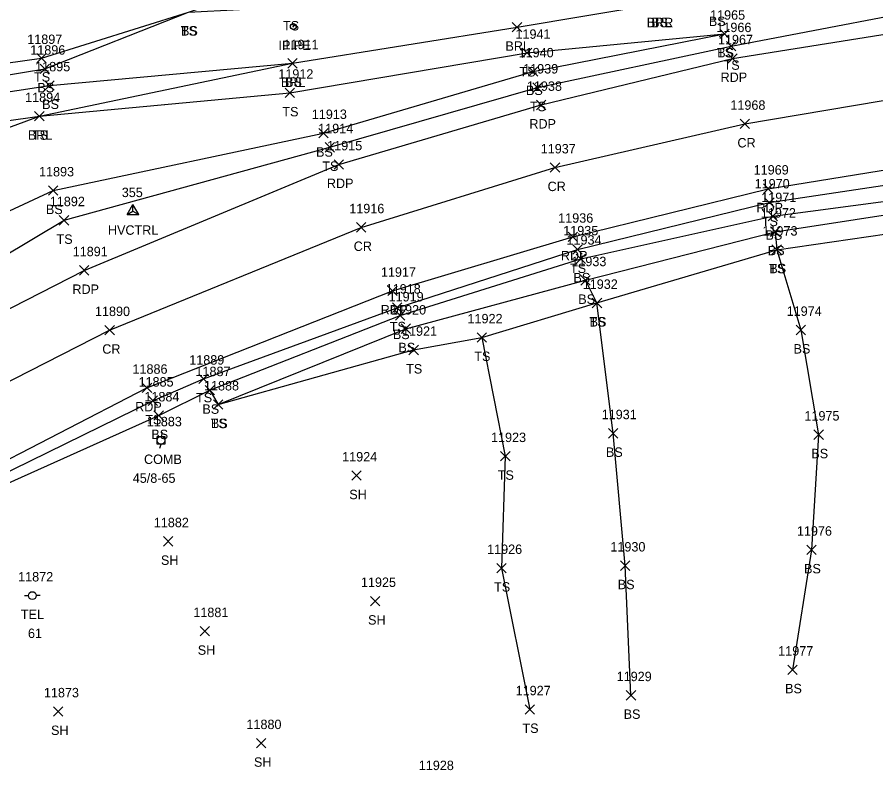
# Model space of a CAD drawing. Extents: x 1475671 to 1477951, y 592661 to 593821.
# Drawn here: x 1477263.9 to 1477446.2, y 593564.8 to 593725.6 of the extents above; entities that cross this region are included whole.
import ezdxf

# ---------------------------------------------------------------- set-up
doc = ezdxf.new("R2010")
doc.units = 0
for name, color, linetype in [('C_A', 7, 'Continuous'), ('C_I', 7, 'Continuous'), ('CPSM', 7, 'Continuous'), ('L_A', 7, 'Continuous'), ('L_I', 7, 'Continuous'), ('L_TIC', 7, 'Continuous'), ('LABL', 7, 'Continuous'), ('LELB', 7, 'Continuous'), ('M_A', 7, 'Continuous'), ('MPIP', 7, 'Continuous'), ('P_A', 7, 'Continuous'), ('P_I', 7, 'Continuous'), ('P_TIC', 7, 'Continuous'), ('PET', 7, 'Continuous'), ('PRC', 7, 'Continuous'), ('U_A', 7, 'Continuous'), ('U_C', 7, 'Continuous'), ('U_I', 7, 'Continuous'), ('UP', 7, 'Continuous')]:
    doc.layers.add(name, color=color, linetype=linetype)

msp = doc.modelspace()

# ---------------------------------------------------------------- linework, layer by layer
at = {"layer": 'CPSM'}
for p, q in [((1477287.25, 593683.69), (1477288.5, 593685.85)), ((1477287.25, 593683.69), (1477288.5, 593684.41)), ((1477289.75, 593683.69), (1477288.5, 593685.85)), ((1477288.5, 593684.41), (1477288.5, 593685.85)), ((1477288.5, 593684.41), (1477288.5, 593684.41)), ((1477288.5, 593684.41), (1477289.75, 593683.69)), ((1477287.25, 593683.69), (1477289.75, 593683.69))]:
    msp.add_line(p, q, dxfattribs=at)
at = {"layer": 'L_TIC'}
for points in [[(1477369.03, 593722.46), (1477371.03, 593724.46)], [(1477371.03, 593722.46), (1477369.03, 593724.46)], [(1477413.08, 593721.06), (1477415.08, 593723.06)], [(1477415.08, 593721.06), (1477413.08, 593723.06)], [(1477413.08, 593721.06), (1477415.08, 593723.06)], [(1477415.08, 593721.06), (1477413.08, 593723.06)], [(1477371.15, 593717.01), (1477373.15, 593719.01)], [(1477373.15, 593717.01), (1477371.15, 593719.01)], [(1477371.15, 593717.01), (1477373.15, 593719.01)], [(1477373.15, 593717.01), (1477371.15, 593719.01)], [(1477414.47, 593718.43), (1477416.47, 593720.43)], [(1477416.47, 593718.43), (1477414.47, 593720.43)], [(1477268.09, 593715.91), (1477270.09, 593717.91)], [(1477270.09, 593715.91), (1477268.09, 593717.91)], [(1477268.77, 593713.64), (1477270.77, 593715.64)], [(1477270.77, 593713.64), (1477268.77, 593715.64)], [(1477321.35, 593714.8), (1477323.35, 593716.8)], [(1477323.35, 593714.8), (1477321.35, 593716.8)], [(1477321.35, 593714.8), (1477323.35, 593716.8)], [(1477323.35, 593714.8), (1477321.35, 593716.8)], [(1477372.48, 593713.07), (1477374.48, 593715.07)], [(1477374.48, 593713.07), (1477372.48, 593715.07)], [(1477372.48, 593713.07), (1477374.48, 593715.07)], [(1477374.48, 593713.07), (1477372.48, 593715.07)], [(1477269.78, 593710.1), (1477271.78, 593712.1)], [(1477271.78, 593710.1), (1477269.78, 593712.1)], [(1477373.36, 593709.64), (1477375.36, 593711.64)], [(1477375.36, 593709.64), (1477373.36, 593711.64)], [(1477320.81, 593708.54), (1477322.81, 593710.54)], [(1477322.81, 593708.54), (1477320.81, 593710.54)], [(1477267.63, 593703.57), (1477269.63, 593705.57)], [(1477269.63, 593703.57), (1477267.63, 593705.57)], [(1477267.63, 593703.57), (1477269.63, 593705.57)], [(1477269.63, 593703.57), (1477267.63, 593705.57)], [(1477327.93, 593699.99), (1477329.93, 593701.99)], [(1477329.93, 593699.99), (1477327.93, 593701.99)], [(1477329.28, 593696.97), (1477331.28, 593698.97)], [(1477331.28, 593696.97), (1477329.28, 593698.97)], [(1477270.58, 593687.8), (1477272.58, 593689.8)], [(1477272.58, 593687.8), (1477270.58, 593689.8)], [(1477422.58, 593685.25), (1477424.58, 593687.25)], [(1477424.58, 593685.25), (1477422.58, 593687.25)], [(1477423.33, 593682.35), (1477425.33, 593684.35)], [(1477425.33, 593682.35), (1477423.33, 593684.35)], [(1477272.87, 593681.48), (1477274.87, 593683.48)], [(1477274.87, 593681.48), (1477272.87, 593683.48)], [(1477423.82, 593679.06), (1477425.82, 593681.06)], [(1477425.82, 593679.06), (1477423.82, 593681.06)], [(1477423.82, 593679.06), (1477425.82, 593681.06)], [(1477425.82, 593679.06), (1477423.82, 593681.06)], [(1477381.86, 593675.29), (1477383.86, 593677.29)], [(1477383.86, 593675.29), (1477381.86, 593677.29)], [(1477424.15, 593675.24), (1477426.15, 593677.24)], [(1477426.15, 593675.24), (1477424.15, 593677.24)], [(1477424.15, 593675.24), (1477426.15, 593677.24)], [(1477426.15, 593675.24), (1477424.15, 593677.24)], [(1477382.56, 593673.31), (1477384.56, 593675.31)], [(1477384.56, 593673.31), (1477382.56, 593675.31)], [(1477383.59, 593668.74), (1477385.59, 593670.74)], [(1477385.59, 593668.74), (1477383.59, 593670.74)], [(1477383.59, 593668.74), (1477385.59, 593670.74)], [(1477385.59, 593668.74), (1477383.59, 593670.74)], [(1477386, 593663.93), (1477388, 593665.93)], [(1477388, 593663.93), (1477386, 593665.93)], [(1477386, 593663.93), (1477388, 593665.93)], [(1477388, 593663.93), (1477386, 593665.93)], [(1477343.61, 593662.93), (1477345.61, 593664.93)], [(1477345.61, 593662.93), (1477343.61, 593664.93)], [(1477344.23, 593661.26), (1477346.23, 593663.26)], [(1477346.23, 593661.26), (1477344.23, 593663.26)], [(1477345.4, 593658.48), (1477347.4, 593660.48)], [(1477347.4, 593658.48), (1477345.4, 593660.48)], [(1477361.55, 593656.61), (1477363.55, 593658.61)], [(1477363.55, 593656.61), (1477361.55, 593658.61)], [(1477361.55, 593656.61), (1477363.55, 593658.61)], [(1477363.55, 593656.61), (1477361.55, 593658.61)], [(1477429.29, 593658.2), (1477431.29, 593660.2)], [(1477431.29, 593658.2), (1477429.29, 593660.2)], [(1477347.08, 593653.96), (1477349.08, 593655.96)], [(1477349.08, 593653.96), (1477347.08, 593655.96)], [(1477302.48, 593647.85), (1477304.48, 593649.85)], [(1477304.48, 593647.85), (1477302.48, 593649.85)], [(1477303.8, 593645.41), (1477305.8, 593647.41)], [(1477305.8, 593645.41), (1477303.8, 593647.41)], [(1477303.8, 593645.41), (1477305.8, 593647.41)], [(1477305.8, 593645.41), (1477303.8, 593647.41)], [(1477291.71, 593643.19), (1477293.71, 593645.19)], [(1477293.71, 593643.19), (1477291.71, 593645.19)], [(1477305.6, 593642.37), (1477307.6, 593644.37)], [(1477307.6, 593642.37), (1477305.6, 593644.37)], [(1477305.6, 593642.37), (1477307.6, 593644.37)], [(1477307.6, 593642.37), (1477305.6, 593644.37)], [(1477292.96, 593640.04), (1477294.96, 593642.04)], [(1477294.96, 593640.04), (1477292.96, 593642.04)], [(1477389.46, 593636.27), (1477391.46, 593638.27)], [(1477391.46, 593636.27), (1477389.46, 593638.27)], [(1477433.06, 593635.98), (1477435.06, 593637.98)], [(1477435.06, 593635.98), (1477433.06, 593637.98)], [(1477366.54, 593631.41), (1477368.54, 593633.41)], [(1477368.54, 593631.41), (1477366.54, 593633.41)], [(1477334.93, 593627.29), (1477336.93, 593629.29)], [(1477336.93, 593627.29), (1477334.93, 593629.29)], [(1477294.95, 593613.34), (1477296.95, 593615.34)], [(1477296.95, 593613.34), (1477294.95, 593615.34)], [(1477431.52, 593611.54), (1477433.52, 593613.54)], [(1477433.52, 593611.54), (1477431.52, 593613.54)], [(1477365.75, 593607.66), (1477367.75, 593609.66)], [(1477367.75, 593607.66), (1477365.75, 593609.66)], [(1477391.96, 593608.18), (1477393.96, 593610.18)], [(1477393.96, 593608.18), (1477391.96, 593610.18)], [(1477338.92, 593600.66), (1477340.92, 593602.66)], [(1477340.92, 593600.66), (1477338.92, 593602.66)], [(1477302.78, 593594.26), (1477304.78, 593596.26)], [(1477304.78, 593594.26), (1477302.78, 593596.26)], [(1477427.49, 593586.09), (1477429.49, 593588.09)], [(1477429.49, 593586.09), (1477427.49, 593588.09)], [(1477393.22, 593580.66), (1477395.22, 593582.66)], [(1477395.22, 593580.66), (1477393.22, 593582.66)], [(1477271.62, 593577.23), (1477273.62, 593579.23)], [(1477273.62, 593577.23), (1477271.62, 593579.23)], [(1477371.77, 593577.67), (1477373.77, 593579.67)], [(1477373.77, 593577.67), (1477371.77, 593579.67)], [(1477314.7, 593570.49), (1477316.7, 593572.49)], [(1477316.7, 593570.49), (1477314.7, 593572.49)]]:
    msp.add_lwpolyline(points, dxfattribs=at)
at = {"layer": 'LABL'}
msp.add_lwpolyline([(1477070.39, 593692.41), (1477067.99, 593679.34), (1477071.39, 593656.39), (1477069.25, 593632), (1477071.86, 593601.77), (1477082.98, 593597.36), (1477107.11, 593607.76), (1477119.12, 593610.41), (1477150.77, 593620.61), (1477191.19, 593657.06), (1477226.2, 593667.71), (1477230.98, 593680.18), (1477228.88, 593689.92), (1477268.63, 593704.57), (1477322.35, 593715.8), (1477370.03, 593723.46), (1477400.06, 593728.47)], dxfattribs=at)
at = {"layer": 'LELB'}
for points in [[(1477137.36, 593693.23), (1477131.81, 593697.29), (1477156.86, 593699.4), (1477177.34, 593702.04), (1477224.05, 593707.11), (1477269.77, 593714.64), (1477300.26, 593726.69), (1477319.36, 593733.18), (1477363.24, 593739.29), (1477396.53, 593752.37), (1477463.79, 593746.86), (1477493.79, 593749.99), (1477520.39, 593749.88), (1477564.42, 593755.36)], [(1477132.94, 593704.7), (1477159.3, 593706.23), (1477177.13, 593706.7), (1477223.11, 593710.47), (1477269.09, 593716.91), (1477300.26, 593726.69), (1477321.94, 593727.78), (1477366.61, 593733.7), (1477398.67, 593744.99), (1477464.61, 593743.02), (1477494.58, 593745.49), (1477521.06, 593747.41), (1477564.24, 593751.76)], [(1477064.35, 593692.56), (1477062.58, 593680.23), (1477060.36, 593654.33), (1477057.44, 593632.54), (1477055.72, 593611.01), (1477054.29, 593601.33), (1477056.65, 593583.23), (1477068.97, 593572.83), (1477078.55, 593566.18), (1477107.01, 593572.34), (1477124.47, 593584.78), (1477157.24, 593607.25), (1477189.46, 593630.34), (1477226.15, 593653.98), (1477273.87, 593682.48), (1477330.28, 593697.97), (1477374.36, 593710.64), (1477415.47, 593719.43), (1477468.07, 593729.59), (1477496.83, 593733.35), (1477522.49, 593736.3), (1477565.44, 593741.31)], [(1477372.15, 593718.01), (1477414.08, 593722.06)], [(1477373.48, 593714.07), (1477414.08, 593722.06)], [(1477142.24, 593688.09), (1477158.48, 593688.13), (1477179.67, 593690.84), (1477223.11, 593698.14), (1477268.63, 593704.57), (1477321.81, 593709.54), (1477372.15, 593718.01)], [(1477153.33, 593661.78), (1477154.42, 593667.71), (1477142.24, 593688.09), (1477137.36, 593693.23), (1477156.82, 593693.93), (1477178.28, 593697.28), (1477223.08, 593703.78), (1477270.78, 593711.1), (1477322.35, 593715.8)], [(1477062.54, 593595.93), (1477087.17, 593588.89), (1477102.97, 593589.96), (1477119.12, 593610.41), (1477134.07, 593632.51), (1477152.16, 593650.25), (1477153.66, 593657.12), (1477163.06, 593661.03), (1477185.94, 593664.32), (1477226.2, 593667.71), (1477271.58, 593688.8), (1477328.93, 593700.99), (1477373.48, 593714.07)], [(1477055.95, 593478.11), (1477074.78, 593497.41), (1477099.84, 593518.79), (1477134.38, 593545.79), (1477166.94, 593568.76), (1477207.75, 593594.56), (1477237.01, 593614.27), (1477256.43, 593624.24), (1477293.96, 593641.04), (1477304.8, 593646.41), (1477345.23, 593662.26), (1477383.56, 593674.31), (1477424.33, 593683.35), (1477474.43, 593689.99), (1477503.05, 593695.22), (1477531.19, 593697.25), (1477568.45, 593701.91)], [(1477304.8, 593646.41), (1477306.6, 593643.37), (1477346.4, 593659.48), (1477384.59, 593669.74), (1477424.82, 593680.06), (1477474.88, 593687.75), (1477503.13, 593692.48), (1477532.29, 593694.01), (1477568.38, 593699.61)], [(1476970.32, 593415.97), (1476999.65, 593441.77), (1477011.08, 593451.76), (1477020.84, 593458.8), (1477029.39, 593465.42), (1477043.63, 593475.69), (1477052.67, 593482.42), (1477071.54, 593501.59), (1477097.81, 593522.54), (1477132.73, 593548.15), (1477165.81, 593571.26), (1477206.03, 593598.34), (1477236.29, 593616.29), (1477255.56, 593625.95), (1477292.71, 593644.19), (1477303.48, 593648.85), (1477344.61, 593663.93), (1477382.86, 593676.29), (1477423.58, 593686.25), (1477474.01, 593693.84)], [(1477306.6, 593643.37), (1477348.08, 593654.96), (1477362.55, 593657.61), (1477387, 593664.93), (1477425.15, 593676.24), (1477475.77, 593683.58), (1477504.96, 593684.6), (1477533.33, 593685.93), (1477567.87, 593690.8)], [(1477424.82, 593680.06), (1477425.15, 593676.24), (1477430.29, 593659.2), (1477434.06, 593636.98), (1477432.52, 593612.54), (1477428.49, 593587.09)], [(1477394.22, 593581.66), (1477392.96, 593609.18), (1477390.46, 593637.27), (1477387, 593664.93), (1477384.59, 593669.74)], [(1477362.55, 593657.61), (1477367.54, 593632.41), (1477366.75, 593608.66), (1477372.77, 593578.67)]]:
    msp.add_lwpolyline(points, dxfattribs=at)
at = {"layer": 'MPIP'}
for radius in [0.625, 0.0833]:
    msp.add_circle((1477322.55, 593723.62), radius, dxfattribs=at)
at = {"layer": 'P_TIC'}
for points in [[(1477414.75, 593715.85), (1477416.75, 593717.85)], [(1477416.75, 593715.85), (1477414.75, 593717.85)], [(1477374.16, 593705.96), (1477376.16, 593707.96)], [(1477376.16, 593705.96), (1477374.16, 593707.96)], [(1477417.39, 593701.94), (1477419.39, 593703.94)], [(1477419.39, 593701.94), (1477417.39, 593703.94)], [(1477331.19, 593693.33), (1477333.19, 593695.33)], [(1477333.19, 593693.33), (1477331.19, 593695.33)], [(1477377.09, 593692.68), (1477379.09, 593694.68)], [(1477379.09, 593692.68), (1477377.09, 593694.68)], [(1477422.34, 593688.19), (1477424.34, 593690.19)], [(1477424.34, 593688.19), (1477422.34, 593690.19)], [(1477335.93, 593679.98), (1477337.93, 593681.98)], [(1477337.93, 593679.98), (1477335.93, 593681.98)], [(1477380.85, 593677.97), (1477382.85, 593679.97)], [(1477382.85, 593677.97), (1477380.85, 593679.97)], [(1477277.16, 593670.86), (1477279.16, 593672.86)], [(1477279.16, 593670.86), (1477277.16, 593672.86)], [(1477342.59, 593666.49), (1477344.59, 593668.49)], [(1477344.59, 593666.49), (1477342.59, 593668.49)], [(1477282.55, 593658.16), (1477284.55, 593660.16)], [(1477284.55, 593658.16), (1477282.55, 593660.16)], [(1477290.48, 593645.91), (1477292.48, 593647.91)], [(1477292.48, 593645.91), (1477290.48, 593647.91)]]:
    msp.add_lwpolyline(points, dxfattribs=at)
at = {"layer": 'PET'}
for points in [[(1476922.98, 593419.08), (1476952.36, 593443.37), (1476980.99, 593467.2), (1477001.29, 593483.18), (1477023.09, 593498.99), (1477048.41, 593522.27), (1477069.64, 593540.85), (1477092.48, 593558.05), (1477107.82, 593567.96), (1477124.14, 593580.14), (1477159.25, 593604.27), (1477192.28, 593625.33), (1477229.26, 593646.84), (1477278.16, 593671.86), (1477332.19, 593694.33), (1477375.16, 593706.96), (1477415.75, 593716.85), (1477468.99, 593725.32)], [(1476967.73, 593418.7), (1476998.53, 593444.47), (1477010.16, 593454.71), (1477020.69, 593463.7), (1477040.87, 593480.17), (1477070.05, 593503.84), (1477096.22, 593524.5), (1477130.86, 593550.96), (1477164.87, 593573.97), (1477205.52, 593600.91), (1477235.56, 593618.03), (1477291.48, 593646.91), (1477343.59, 593667.49), (1477381.85, 593678.97), (1477423.34, 593689.19), (1477473.94, 593697.4)]]:
    msp.add_lwpolyline(points, dxfattribs=at)
at = {"layer": 'PRC'}
msp.add_lwpolyline([(1476934.06, 593407.68), (1476963.46, 593432.81), (1476989.48, 593455.26), (1477029.64, 593488.99), (1477062.06, 593515.29), (1477088.32, 593536.02), (1477123.8, 593562.56), (1477162.82, 593589.95), (1477199.33, 593613.78), (1477232.88, 593633.31), (1477283.55, 593659.16), (1477336.93, 593680.98), (1477378.09, 593693.68), (1477418.39, 593702.94), (1477470.82, 593711.77)], dxfattribs=at)
at = {"layer": 'UP'}
for p, q in [((1477294.71, 593637.43), (1477294.46, 593636.6)), ((1477293.63, 593634.93), (1477293.63, 593636.6)), ((1477293.63, 593636.6), (1477295.3, 593636.6)), ((1477295.3, 593634.93), (1477293.63, 593634.93)), ((1477294.21, 593634.1), (1477294.46, 593634.93)), ((1477294.46, 593635.76), (1477294.46, 593635.76)), ((1477295.3, 593636.6), (1477295.3, 593634.93)), ((1477265.49, 593602.82), (1477266.32, 593602.82)), ((1477267.15, 593602.82), (1477267.15, 593602.82)), ((1477268.82, 593602.82), (1477267.98, 593602.82)), ((1477267.98, 593602.82), (1477267.98, 593602.82)), ((1477268.82, 593602.82), (1477268.82, 593602.82))]:
    msp.add_line(p, q, dxfattribs=at)
for centre in [(1477294.46, 593635.76), (1477267.15, 593602.82)]:
    msp.add_circle(centre, 0.833, dxfattribs=at)

# ---------------------------------------------------------------- texts
at = {"layer": 'C_A'}
msp.add_text('HVCTRL', height=2, dxfattribs=at).set_placement((1477283.19, 593679.41))
at = {"layer": 'C_I'}
msp.add_text('355', height=2, dxfattribs=at).set_placement((1477286.13, 593687.41))
at = {"layer": 'L_A'}
for s, p in [('TS', (1477320.35, 593722.78)), ('BRR', (1477397.55, 593723.47)), ('BRL', (1477397.61, 593723.47)), ('BS', (1477398.5, 593723.47)), ('BS', (1477410.74, 593723.71)), ('TS', (1477298.67, 593721.69)), ('BS', (1477298.7, 593721.69)), ('BRL', (1477367.57, 593718.46)), ('TS', (1477412.49, 593717.06)), ('BS', (1477412.52, 593717.06)), ('TS', (1477413.88, 593714.43)), ('TS', (1477267.5, 593711.91)), ('TS', (1477370.56, 593713.01)), ('TS', (1477370.56, 593713.01)), ('BS', (1477268.21, 593709.64)), ('BRL', (1477319.89, 593710.8)), ('BS', (1477320.79, 593710.8)), ('BS', (1477371.92, 593709.07)), ('BS', (1477371.92, 593709.07)), ('BS', (1477269.22, 593706.1)), ('TS', (1477320.22, 593704.54)), ('TS', (1477372.77, 593705.64)), ('BRL', (1477266.18, 593699.57)), ('TS', (1477267.04, 593699.57)), ('BS', (1477327.37, 593695.99)), ('TS', (1477328.69, 593692.97)), ('BS', (1477270.02, 593683.8)), ('TS', (1477421.99, 593681.25)), ('TS', (1477272.28, 593677.48)), ('BS', (1477422.77, 593678.35)), ('BS', (1477423.26, 593675.06)), ('BS', (1477423.26, 593675.06)), ('TS', (1477381.27, 593671.29)), ('TS', (1477423.56, 593671.24)), ('BS', (1477423.59, 593671.24)), ('BS', (1477382, 593669.31)), ('BS', (1477383.03, 593664.74)), ('BS', (1477383.03, 593664.74)), ('TS', (1477343.02, 593658.93)), ('TS', (1477385.41, 593659.93)), ('BS', (1477385.44, 593659.93)), ('BS', (1477343.67, 593657.26)), ('BS', (1477344.84, 593654.48)), ('BS', (1477428.73, 593654.2)), ('TS', (1477360.96, 593652.61)), ('TS', (1477360.96, 593652.61)), ('TS', (1477346.49, 593649.96)), ('TS', (1477301.89, 593643.85)), ('BS', (1477303.24, 593641.41)), ('BS', (1477303.24, 593641.41)), ('TS', (1477291.12, 593639.19)), ('TS', (1477305.01, 593638.37)), ('BS', (1477305.04, 593638.37)), ('BS', (1477292.4, 593636.04)), ('BS', (1477388.9, 593632.27)), ('BS', (1477432.5, 593631.98)), ('TS', (1477365.94, 593627.41)), ('SH', (1477334.42, 593623.29)), ('SH', (1477294.44, 593609.34)), ('BS', (1477430.96, 593607.54)), ('BS', (1477391.41, 593604.18)), ('TS', (1477365.16, 593603.66)), ('SH', (1477338.41, 593596.66)), ('SH', (1477302.26, 593590.26)), ('BS', (1477426.93, 593582.09)), ('BS', (1477392.66, 593576.66)), ('SH', (1477271.11, 593573.23)), ('TS', (1477371.18, 593573.67)), ('SH', (1477314.19, 593566.49))]:
    msp.add_text(s, height=2, dxfattribs=at).set_placement(p)
at = {"layer": 'L_I'}
for s, p in [('11965', (1477411.01, 593725.06)), ('11965', (1477411.01, 593725.06)), ('11966', (1477412.35, 593722.43)), ('11941', (1477369.7, 593721.01)), ('11941', (1477369.7, 593721.01)), ('11897', (1477266.06, 593719.91)), ('11911', (1477320.46, 593718.8)), ('11911', (1477320.46, 593718.8)), ('11896', (1477266.7, 593717.64)), ('11940', (1477370.37, 593717.07)), ('11940', (1477370.37, 593717.07)), ('11895', (1477267.75, 593714.1)), ('11939', (1477371.33, 593713.64)), ('11912', (1477319.36, 593712.54)), ('11894', (1477265.61, 593707.57)), ('11894', (1477265.61, 593707.57)), ('11913', (1477326.47, 593703.99)), ('11914', (1477327.82, 593700.97)), ('11893', (1477268.56, 593691.8)), ('11970', (1477420.47, 593689.25)), ('11971', (1477421.87, 593686.35)), ('11892', (1477270.85, 593685.48)), ('11972', (1477421.79, 593683.06)), ('11972', (1477421.79, 593683.06)), ('11935', (1477379.84, 593679.29)), ('11973', (1477422.13, 593679.24)), ('11973', (1477422.13, 593679.24)), ('11934', (1477380.53, 593677.31)), ('11933', (1477381.56, 593672.74)), ('11933', (1477381.56, 593672.74)), ('11932', (1477383.98, 593667.93)), ('11932', (1477383.98, 593667.93)), ('11918', (1477342.15, 593666.93)), ('11919', (1477342.77, 593665.26)), ('11920', (1477343.29, 593662.48)), ('11974', (1477427.27, 593662.2)), ('11922', (1477359.52, 593660.61)), ('11922', (1477359.52, 593660.61)), ('11921', (1477345.62, 593657.96)), ('11889', (1477300.45, 593651.85)), ('11887', (1477301.77, 593649.41)), ('11887', (1477301.77, 593649.41)), ('11885', (1477289.69, 593647.19)), ('11888', (1477303.58, 593646.37)), ('11888', (1477303.58, 593646.37)), ('11884', (1477290.93, 593644.04)), ('11931', (1477388, 593640.27)), ('11975', (1477431.04, 593639.98)), ('11923', (1477364.51, 593635.41)), ('11924', (1477332.91, 593631.29)), ('11882', (1477292.93, 593617.34)), ('11976', (1477429.44, 593615.54)), ('11926', (1477363.68, 593611.66)), ('11930', (1477389.85, 593612.18)), ('11925', (1477336.9, 593604.66)), ('11881', (1477301.32, 593598.26)), ('11977', (1477425.47, 593590.09)), ('11929', (1477391.18, 593584.66)), ('11873', (1477269.6, 593581.23)), ('11927', (1477369.74, 593581.67)), ('11880', (1477312.59, 593574.49)), ('11928', (1477349.18, 593565.79))]:
    msp.add_text(s, height=2, dxfattribs=at).set_placement(p)
at = {"layer": 'M_A'}
msp.add_text('IPIPE', height=2, dxfattribs=at).set_placement((1477319.39, 593718.62))
at = {"layer": 'P_A'}
for s, p in [('RDP', (1477413.24, 593711.85)), ('RDP', (1477372.65, 593701.96)), ('CR', (1477416.82, 593697.94)), ('RDP', (1477329.67, 593689.33)), ('CR', (1477376.52, 593688.68)), ('RDP', (1477420.83, 593684.19)), ('CR', (1477335.36, 593675.98)), ('RDP', (1477379.34, 593673.97)), ('RDP', (1477275.65, 593666.86)), ('RDP', (1477341.08, 593662.49)), ('CR', (1477281.99, 593654.16)), ('RDP', (1477288.97, 593641.91))]:
    msp.add_text(s, height=2, dxfattribs=at).set_placement(p)
at = {"layer": 'P_I'}
for s, p in [('11967', (1477412.68, 593719.85)), ('11938', (1477372.13, 593709.96)), ('11968', (1477415.32, 593705.94)), ('11915', (1477329.73, 593697.33)), ('11937', (1477375.06, 593696.68)), ('11969', (1477420.26, 593692.19)), ('11916', (1477334.42, 593683.98)), ('11936', (1477378.77, 593681.97)), ('11891', (1477275.71, 593674.86)), ('11917', (1477341.13, 593670.49)), ('11890', (1477280.44, 593662.16)), ('11886', (1477288.4, 593649.91))]:
    msp.add_text(s, height=2, dxfattribs=at).set_placement(p)
at = {"layer": 'U_A'}
for s, p in [('COMB', (1477290.85, 593630.76)), ('TEL', (1477264.71, 593597.82))]:
    msp.add_text(s, height=2, dxfattribs=at).set_placement(p)
at = {"layer": 'U_C'}
for s, p in [('45/8-65', (1477288.46, 593626.76)), ('61', (1477266.21, 593593.82))]:
    msp.add_text(s, height=2, dxfattribs=at).set_placement(p)
at = {"layer": 'U_I'}
for s, p in [('11883', (1477291.44, 593638.76)), ('11872', (1477264.13, 593605.82))]:
    msp.add_text(s, height=2, dxfattribs=at).set_placement(p)

doc.saveas('drawing.dxf')
